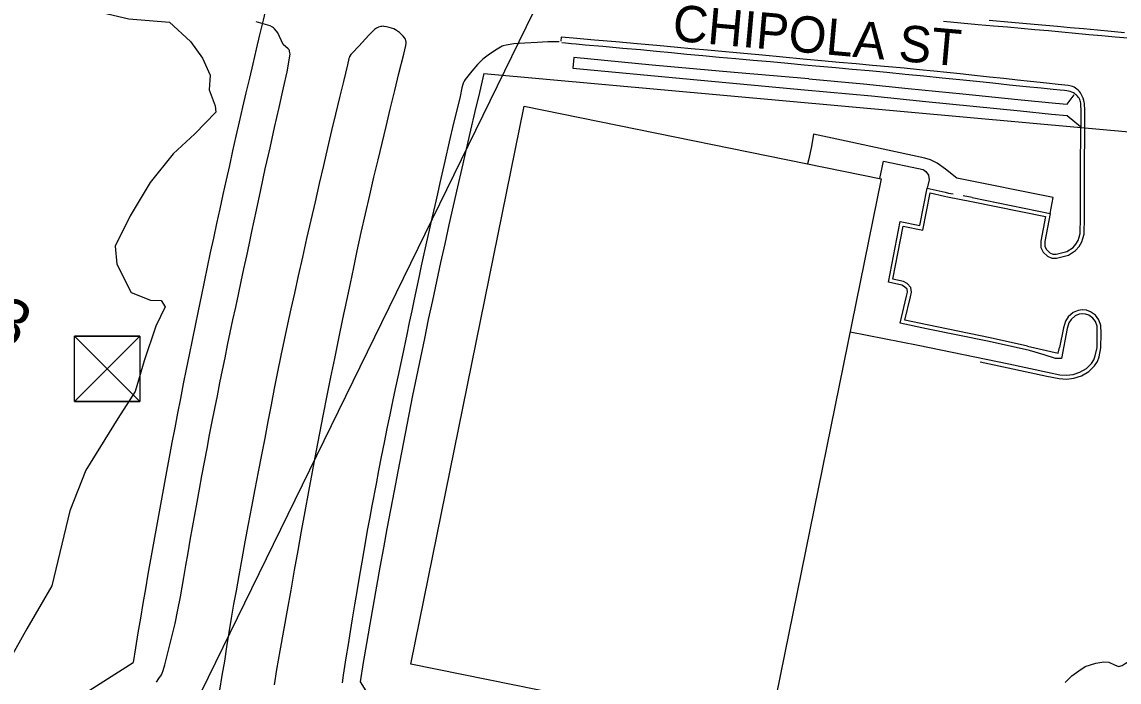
# Model space of a CAD drawing. Extents: x 1517485 to 1521905, y 636528 to 640355.
# Drawn here: x 1520407.4 to 1520890.3, y 638499.8 to 638790.2 of the extents above; entities that cross this region are included whole.
import ezdxf

# ---------------------------------------------------------------- set-up
doc = ezdxf.new("R2010")
doc.units = 0
for name, color, linetype in [('CTL Vertical Benchmark CELL', 7, 'Continuous'), ('CTL Vertical Benchmark Text', 7, 'Continuous'), ('Exist Building', 7, 'Continuous'), ('Exist Hydro Stream or Body of Water', 7, 'Continuous'), ('Exist Other Culture Area Outline', 7, 'Continuous'), ('Exist Right of Way Line', 7, 'Continuous'), ('Exist Roads Curbs', 7, 'Continuous'), ('Exist Roads EOP', 7, 'Continuous'), ('Exist Roads EOP Other', 7, 'Continuous'), ('Exist Roads EOP Text', 7, 'Continuous'), ('Exist Vegetation Woods Line', 7, 'Continuous'), ('Scratch_Level_3', 7, 'Continuous')]:
    doc.layers.add(name, color=color, linetype=linetype)

msp = doc.modelspace()

# ---------------------------------------------------------------- linework, layer by layer
at = {"layer": 'CTL Vertical Benchmark CELL'}
msp.add_line((1520444.93, 638637.58), (1520444.93, 638637.58), dxfattribs=at)
msp.add_lwpolyline([(1520430.53, 638651.93), (1520459.28, 638651.93), (1520459.28, 638623.18), (1520430.53, 638623.18)], close=True, dxfattribs=at)
for points in [[(1520459.28, 638651.93), (1520430.53, 638623.18), (1520444.91, 638637.55), (1520459.28, 638623.18), (1520430.53, 638651.93)], [(1520444.91, 638637.55), (1520459.28, 638651.93), (1520430.53, 638651.93), (1520444.91, 638637.55)], [(1520444.91, 638637.55), (1520430.53, 638623.18), (1520459.28, 638623.18), (1520444.91, 638637.55)]]:
    msp.add_lwpolyline(points, dxfattribs=at)
at = {"layer": 'Exist Building'}
msp.add_lwpolyline([(1520578.55, 638507.74), (1520628.44, 638753.1), (1520785.56, 638721.15), (1520735.68, 638475.79)], close=True, dxfattribs=at)
at = {"layer": 'Exist Hydro Stream or Body of Water'}
msp.add_lwpolyline([(1520866.57, 638499.66), (1520869.57, 638502.49), (1520872.64, 638504.76), (1520875.45, 638506.64), (1520880.11, 638508.14), (1520883.63, 638508.75), (1520885.89, 638508.59), (1520888.28, 638507.42), (1520890.12, 638506.62), (1520891.66, 638507.02), (1520892.98, 638507.95), (1520895.65, 638509.56), (1520898.1, 638509.85), (1520907.34, 638509.14), (1520912.79, 638508.11), (1520914.82, 638507.12), (1520917.46, 638504.35), (1520918.38, 638503.18), (1520919.28, 638502.74), (1520920.19, 638502.53), (1520924.87, 638502.08), (1520928.77, 638502.68), (1520932, 638501.95), (1520941, 638498.41)], dxfattribs=at)
at = {"layer": 'Exist Other Culture Area Outline'}
for points in [[(1520859.93, 638705.96), (1520861.34, 638712.91), (1520818.96, 638721.5), (1520813.88, 638725.42), (1520810.21, 638728.01), (1520807.32, 638729.54), (1520804.89, 638730.29), (1520770.19, 638737.68), (1520755.81, 638740.82), (1520754.87, 638735.46)], [(1520754.87, 638735.46), (1520753.55, 638729.42), (1520753.22, 638727.73)], [(1520785.04, 638721.26), (1520786.62, 638728.93), (1520802.09, 638725.66), (1520804.1, 638725.25), (1520805.3, 638724.44), (1520806.38, 638722.81), (1520806.75, 638720.81), (1520805.89, 638717.12)]]:
    msp.add_lwpolyline(points, dxfattribs=at)
at = {"layer": 'Exist Right of Way Line'}
for p, q in [((1520610.77, 638767.46), (1521229.82, 638711.56)), ((1520397.94, 638471.31), (1520456.28, 638508.46)), ((1520556.23, 638499.97), (1520592.71, 638441.73))]:
    msp.add_line(p, q, dxfattribs=at)
for radius, start, end in [(3851.74, 164.44356, 170.68088), (3751.74, 166.39166, 170.56172)]:
    msp.add_arc((1524257.18, 637884.74), radius, start, end, dxfattribs=at)
at = {"layer": 'Exist Roads Curbs'}
for p, q in [((1520815.23, 638714.94), (1520817.27, 638714.53)), ((1520825.71, 638712.92), (1520821.66, 638713.68))]:
    msp.add_line(p, q, dxfattribs=at)
for points in [[(1520833.15, 638791), (1520842.96, 638790.11), (1520847.95, 638789.66), (1520852.98, 638789.21), (1520858.05, 638788.76), (1520863.28, 638788.29), (1520868.82, 638787.79), (1520874.65, 638787.26), (1520880.79, 638786.69), (1520886.9, 638786.12), (1520892.68, 638785.58)], [(1520873.63, 638743.58), (1520873.61, 638745.05), (1520873.62, 638746.43), (1520873.65, 638747.85), (1520873.67, 638749.27), (1520873.64, 638750.67), (1520873.59, 638751.93), (1520873.55, 638752.95), (1520873.5, 638753.78), (1520873.45, 638754.42), (1520873.36, 638754.99), (1520873.21, 638755.54), (1520873, 638756.1), (1520872.71, 638756.64), (1520872.36, 638757.15), (1520871.98, 638757.6), (1520871.59, 638757.99), (1520871.2, 638758.33), (1520870.76, 638758.66), (1520870.21, 638759.01), (1520869.55, 638759.32), (1520868.79, 638759.56), (1520868.02, 638759.74), (1520867.32, 638759.86), (1520866.27, 638759.99), (1520864.46, 638760.19), (1520861.25, 638760.51), (1520855.97, 638761.03), (1520849.36, 638761.69), (1520842.11, 638762.44), (1520834.69, 638763.22), (1520827.55, 638763.97), (1520820.28, 638764.74), (1520812.47, 638765.53), (1520804.34, 638766.34), (1520796.16, 638767.13), (1520788.08, 638767.9), (1520780.29, 638768.63), (1520772.8, 638769.31), (1520765.63, 638769.96), (1520758.64, 638770.59), (1520751.69, 638771.23), (1520744.54, 638771.89), (1520736.94, 638772.59), (1520729.2, 638773.29), (1520721.68, 638773.96), (1520714.32, 638774.61), (1520707.08, 638775.27), (1520700.07, 638775.93), (1520693.36, 638776.57), (1520686.66, 638777.21), (1520679.66, 638777.86), (1520671.93, 638778.57), (1520663.03, 638779.36), (1520655.35, 638780.04), (1520651.31, 638780.39), (1520649.36, 638780.56), (1520647.97, 638780.69), (1520646.59, 638780.83), (1520645.03, 638781)], [(1520825.71, 638712.92), (1520859.93, 638705.96), (1520857.66, 638693.63), (1520857.6, 638691.4), (1520858.37, 638690.04), (1520859.84, 638688.63), (1520861.14, 638687.99), (1520862.63, 638687.97), (1520867.28, 638689.22), (1520870.06, 638690.98), (1520871.34, 638692.45), (1520872.33, 638694.11), (1520872.75, 638695.46), (1520873.17, 638697.11), (1520873.3, 638704.23), (1520873.37, 638725.16), (1520873.55, 638743.5)], [(1520771.89, 638653.9), (1520801.84, 638648.02), (1520841.84, 638639.78), (1520858.82, 638636.06), (1520864.19, 638634.99), (1520867.17, 638634.8), (1520870.1, 638635.17), (1520873.04, 638636.1), (1520875.94, 638637.81), (1520878.14, 638639.96), (1520879.27, 638641.62), (1520879.87, 638643.37), (1520880.61, 638647.03), (1520880.71, 638653.23), (1520880.63, 638656.41), (1520879.91, 638658.38), (1520878.72, 638659.95), (1520877.01, 638661.18), (1520875.62, 638661.66), (1520874.17, 638661.81), (1520872.79, 638661.62), (1520871.03, 638660.87), (1520869.23, 638659.3), (1520868.24, 638657.83), (1520867.51, 638655.29), (1520864.98, 638642.14), (1520862.38, 638642.14), (1520857.31, 638643.73), (1520850.83, 638645.61), (1520833.18, 638649.57), (1520805.56, 638655.25), (1520793.92, 638657.67), (1520796.82, 638669.58), (1520797.15, 638671.32), (1520796.99, 638672.58), (1520795.92, 638673.74), (1520794.74, 638674.43), (1520788.8, 638675.76), (1520793.92, 638702.47), (1520802.65, 638700.6), (1520805.89, 638717.12), (1520813.81, 638715.26), (1520815.23, 638714.94)]]:
    msp.add_lwpolyline(points, dxfattribs=at)
at = {"layer": 'Exist Roads EOP'}
for points in [[(1520466.63, 638499.78), (1520467.7, 638501.42), (1520468.75, 638502.98), (1520469.15, 638503.71), (1520469.6, 638504.91), (1520470.26, 638507.35), (1520471.81, 638513.27), (1520473.37, 638519.63), (1520474.8, 638525.53), (1520476.05, 638531.57), (1520477.1, 638537.28), (1520478.6, 638545.74), (1520479.52, 638551.04), (1520480.5, 638556.68), (1520481.48, 638562.29), (1520482.47, 638567.85), (1520483.45, 638573.37), (1520484.46, 638578.95), (1520485.5, 638584.67), (1520486.59, 638590.55), (1520487.72, 638596.57), (1520488.87, 638602.62), (1520490.01, 638608.56), (1520491.15, 638614.39), (1520492.29, 638620.11), (1520493.42, 638625.76), (1520494.54, 638631.38), (1520495.67, 638636.95), (1520496.79, 638642.48), (1520497.93, 638648.01), (1520499.08, 638653.56), (1520500.26, 638659.13), (1520501.46, 638664.72), (1520502.67, 638670.34), (1520503.88, 638675.98), (1520505.1, 638681.64), (1520506.32, 638687.33), (1520507.51, 638692.86), (1520508.61, 638698.05), (1520510.58, 638707.44), (1520512.47, 638716.34), (1520514.51, 638725.58), (1520516.59, 638734.83), (1520518.6, 638743.77), (1520520.57, 638752.53), (1520522.53, 638761.27), (1520524.08, 638768.28), (1520525.07, 638773.41), (1520525.36, 638775.24), (1520525.38, 638775.96), (1520525.34, 638776.64), (1520525.22, 638777.28), (1520525.12, 638777.59), (1520524.97, 638777.88), (1520524.78, 638778.16), (1520524.55, 638778.42), (1520522.42, 638780.25), (1520519.99, 638785.39), (1520519.48, 638786.2), (1520518.56, 638787.21), (1520518.09, 638787.61), (1520517.62, 638787.94), (1520516.58, 638788.47), (1520513.55, 638789.38), (1520510.42, 638790.17)], [(1520518.48, 638498.57), (1520519.64, 638505.27), (1520521.09, 638513.51), (1520522.68, 638522.5), (1520524.27, 638531.41), (1520525.85, 638540.24), (1520527.4, 638549.01), (1520528.94, 638557.68), (1520530.49, 638566.25), (1520532.05, 638574.83), (1520533.66, 638583.57), (1520535.29, 638592.32), (1520536.94, 638600.91), (1520538.57, 638609.36), (1520540.17, 638617.67), (1520541.76, 638625.85), (1520543.37, 638633.93), (1520545.06, 638642.2), (1520546.87, 638650.93), (1520548.69, 638659.6), (1520550.38, 638667.65), (1520551.96, 638675.16), (1520553.43, 638682.22), (1520554.96, 638689.45), (1520556.74, 638697.5), (1520558.63, 638705.85), (1520560.5, 638714), (1520562.34, 638721.91), (1520564.13, 638729.52), (1520565.9, 638736.93), (1520567.67, 638744.22), (1520569.51, 638751.79), (1520571.51, 638760.04), (1520573.32, 638767.49), (1520575.42, 638776.08), (1520576.3, 638779.89), (1520576.45, 638780.83), (1520576.47, 638781.46), (1520576.43, 638781.74), (1520576.38, 638781.99), (1520576.15, 638782.55), (1520575.77, 638783.23), (1520575.21, 638783.99), (1520573.63, 638785.51), (1520572.74, 638786.19), (1520571.85, 638786.76), (1520571.02, 638787.15), (1520569.05, 638787.81), (1520567.92, 638788.1), (1520566.87, 638788.26), (1520566.36, 638788.28), (1520565.85, 638788.26), (1520565.35, 638788.18), (1520564.35, 638787.9), (1520563.42, 638787.47), (1520562.52, 638786.87), (1520560.02, 638784.43), (1520555.62, 638779.55), (1520552.79, 638776.49), (1520552.2, 638775.83), (1520551.74, 638775.15), (1520551.63, 638774.98), (1520551.52, 638774.77), (1520551.32, 638774.11), (1520550.7, 638771.39), (1520548.9, 638763.96), (1520547.2, 638756.97), (1520545.42, 638749.69), (1520543.65, 638742.39), (1520541.86, 638734.86), (1520540.05, 638727.06), (1520538.22, 638719.13), (1520536.38, 638711.09), (1520534.54, 638703.05), (1520532.69, 638695), (1520530.83, 638686.79), (1520528.98, 638678.51), (1520527.29, 638670.93), (1520525.77, 638664.06), (1520524.29, 638657.25), (1520522.82, 638650.4), (1520521.35, 638643.39), (1520519.89, 638636.22), (1520518.45, 638628.98), (1520517.05, 638621.69), (1520515.64, 638614.42), (1520514.23, 638607.16), (1520512.78, 638599.81), (1520511.31, 638592.33), (1520509.84, 638584.7), (1520508.36, 638576.93), (1520506.92, 638569.2), (1520505.53, 638561.55), (1520504.17, 638554), (1520502.85, 638546.63), (1520501.65, 638539.99), (1520500.56, 638534.01), (1520499.52, 638527.94), (1520498.49, 638521.67), (1520497.48, 638515.36), (1520496.47, 638509.04), (1520495.41, 638502.68), (1520494.3, 638496.26)], [(1520894.36, 638783.01), (1520888.57, 638783.54), (1520882.81, 638784.06), (1520877.02, 638784.59), (1520871.13, 638785.13), (1520865.2, 638785.67), (1520859.26, 638786.22), (1520853.29, 638786.77), (1520847.3, 638787.3), (1520841.23, 638787.83), (1520835.04, 638788.38), (1520828.34, 638788.99), (1520820.72, 638789.68), (1520812.98, 638790.38)], [(1520875.25, 638743.6), (1520875.24, 638751.2), (1520875.04, 638754.33), (1520874.81, 638755.59), (1520874.47, 638756.7), (1520873.71, 638758.39), (1520873.31, 638759.01), (1520872.84, 638759.6), (1520872.33, 638760.15), (1520871.76, 638760.65), (1520871.15, 638761.1), (1520870.51, 638761.47), (1520869.86, 638761.76), (1520869.25, 638761.96), (1520867.86, 638762.21), (1520863.53, 638762.73), (1520858.36, 638763.3), (1520851.28, 638764.03), (1520845.65, 638764.63), (1520839.61, 638765.26), (1520833.27, 638765.93), (1520826.69, 638766.65), (1520820.31, 638767.35), (1520814.53, 638767.94), (1520808.77, 638768.52), (1520802.47, 638769.15), (1520795.78, 638769.81), (1520788.9, 638770.45), (1520781.82, 638771.08), (1520774.55, 638771.73), (1520767.07, 638772.41), (1520759.38, 638773.11), (1520751.23, 638773.87), (1520742.36, 638774.71), (1520733.42, 638775.55), (1520725.08, 638776.32), (1520717.07, 638777.05), (1520709.15, 638777.76), (1520701.9, 638778.4), (1520695.94, 638778.95), (1520686.79, 638779.78), (1520678.13, 638780.56), (1520668.81, 638781.39), (1520659.47, 638782.23), (1520649.95, 638783.09), (1520644.72, 638783.56), (1520644.66, 638781.8)], [(1520643.87, 638781.39), (1520638.91, 638781.38), (1520634.12, 638781.19), (1520628.78, 638780.93), (1520623.95, 638780.55), (1520620.48, 638780.04), (1520619.25, 638779.7), (1520618.73, 638779.49), (1520616.54, 638778.17), (1520613.26, 638775.97), (1520610.32, 638773.75), (1520607.87, 638771.42), (1520605.42, 638768.51), (1520603.66, 638766.31), (1520602.55, 638764.9), (1520602.06, 638764.13), (1520601.67, 638763.3), (1520601.08, 638761.15), (1520600.23, 638757.42), (1520598.93, 638751.99), (1520597.34, 638745.61), (1520595.43, 638737.45), (1520593.5, 638729.01), (1520591.37, 638719.49), (1520590.27, 638714.65), (1520589.09, 638709.43), (1520587.83, 638703.88), (1520586.63, 638698.55), (1520585.49, 638693.46), (1520584.34, 638688.22), (1520583.18, 638682.84), (1520582.09, 638677.78), (1520580.03, 638668.17), (1520578.97, 638663.1), (1520577.89, 638657.91), (1520576.8, 638652.71), (1520574.9, 638643.63), (1520572.85, 638634.12), (1520571.7, 638628.82), (1520570.48, 638623.17), (1520569.25, 638617.37), (1520568.02, 638611.42), (1520566.78, 638605.26), (1520565.54, 638598.93), (1520564.36, 638592.83), (1520563.24, 638587.06), (1520561.4, 638577.27), (1520560.49, 638572.39), (1520559.54, 638567.21), (1520557.86, 638557.64), (1520556.99, 638552.51), (1520556.02, 638546.79), (1520554.95, 638540.48), (1520553.82, 638533.75), (1520552.78, 638527.58), (1520551.84, 638522.03), (1520550.91, 638516.27), (1520550, 638510.42), (1520548.84, 638502.85), (1520548.34, 638499.52)]]:
    msp.add_lwpolyline(points, dxfattribs=at)
at = {"layer": 'Exist Roads EOP Other'}
for p, q in [((1520867.52, 638754.03), (1520870.55, 638758.08)), ((1520814.85, 638713.26), (1520825.36, 638711.2))]:
    msp.add_line(p, q, dxfattribs=at)
for points in [[(1520753.75, 638765.11), (1520720.9, 638767.96), (1520684.83, 638771.2), (1520650.28, 638774.61), (1520649.91, 638769.88), (1520699.84, 638765.13), (1520751.92, 638760.26)], [(1520753.75, 638765.11), (1520777.86, 638762.96), (1520797.49, 638760.88), (1520821.51, 638758.53), (1520845.75, 638756.01), (1520862.36, 638754.47), (1520867.52, 638754.03)], [(1520751.92, 638760.26), (1520781.32, 638757.66), (1520805.24, 638755.19), (1520826.1, 638753.21), (1520846.89, 638751.12), (1520860.55, 638749.69), (1520867.43, 638749.1), (1520873.3, 638744.19)], [(1520825.36, 638711.2), (1520857.89, 638704.59), (1520855.91, 638693.81), (1520855.84, 638690.95), (1520856.97, 638688.95), (1520858.82, 638687.17), (1520860.72, 638686.24), (1520862.85, 638686.21), (1520868, 638687.59), (1520871.21, 638689.64), (1520872.76, 638691.41), (1520873.95, 638693.39), (1520874.44, 638694.98), (1520874.92, 638696.88), (1520875.05, 638704.21), (1520875.13, 638725.15), (1520875.31, 638743.49)], [(1520849.95, 638647.56), (1520833.54, 638651.25), (1520805.91, 638656.93), (1520796.01, 638658.99), (1520798.51, 638669.22), (1520798.88, 638671.26), (1520798.63, 638673.34), (1520797.01, 638675.1), (1520795.38, 638676.05), (1520790.8, 638677.07), (1520795.28, 638700.42), (1520804, 638698.55), (1520807.23, 638715.04), (1520813.43, 638713.59), (1520814.85, 638713.26)], [(1520829.22, 638640.63), (1520841.48, 638638.1), (1520858.46, 638634.37), (1520863.96, 638633.28), (1520867.23, 638633.07), (1520870.47, 638633.49), (1520873.75, 638634.52), (1520876.99, 638636.44), (1520879.47, 638638.85), (1520880.82, 638640.84), (1520881.53, 638642.92), (1520882.33, 638646.84), (1520882.43, 638653.24), (1520882.34, 638656.73), (1520881.44, 638659.22), (1520879.93, 638661.2), (1520877.81, 638662.73), (1520875.99, 638663.34), (1520874.15, 638663.54), (1520872.33, 638663.29), (1520870.11, 638662.35), (1520867.93, 638660.45), (1520866.67, 638658.56), (1520865.84, 638655.69), (1520864.17, 638647.01)], [(1520849.95, 638647.56), (1520863.45, 638644.47), (1520864.17, 638647.01)]]:
    msp.add_lwpolyline(points, dxfattribs=at)
at = {"layer": 'Exist Vegetation Woods Line'}
for points in [[(1520408.25, 638799.55), (1520423.18, 638799.14), (1520435.06, 638796.1), (1520454.4, 638791.49), (1520472.27, 638790.07), (1520481.6, 638781.65), (1520486.91, 638774.26), (1520490.25, 638766.8), (1520489.8, 638760.35), (1520492.5, 638753.27), (1520492.69, 638750.56), (1520483.5, 638741.02), (1520473.9, 638732.2), (1520463.82, 638719.62), (1520454.95, 638704.9), (1520448.42, 638691.59), (1520449.15, 638683.69), (1520455.48, 638671.17), (1520463.95, 638667.78), (1520468.69, 638667.71)], [(1520468.69, 638667.71), (1520470.49, 638664.94), (1520466.27, 638656.36), (1520461.21, 638641.17), (1520457.27, 638627.59), (1520449.55, 638615.72), (1520441.92, 638603.46), (1520435.44, 638593)], [(1520435.44, 638593), (1520428.46, 638575.2), (1520420.51, 638542.07), (1520409.58, 638523.26), (1520396.91, 638500.93)]]:
    msp.add_lwpolyline(points, dxfattribs=at)
at = {"layer": 'Scratch_Level_3'}
msp.add_line((1520770.84, 639077.45), (1520017.02, 637536.16), dxfattribs=at)

# ---------------------------------------------------------------- texts
at = {"layer": 'CTL Vertical Benchmark Text'}
msp.add_text('BM3', height=20, rotation=333.9377, dxfattribs=at).set_placement((1520355.36, 638670.25))
at = {"layer": 'Exist Roads EOP Text'}
msp.add_text('CHIPOLA ST', height=16, rotation=354.8975, dxfattribs=at).set_placement((1520693.36, 638781.98))

doc.saveas('drawing.dxf')
